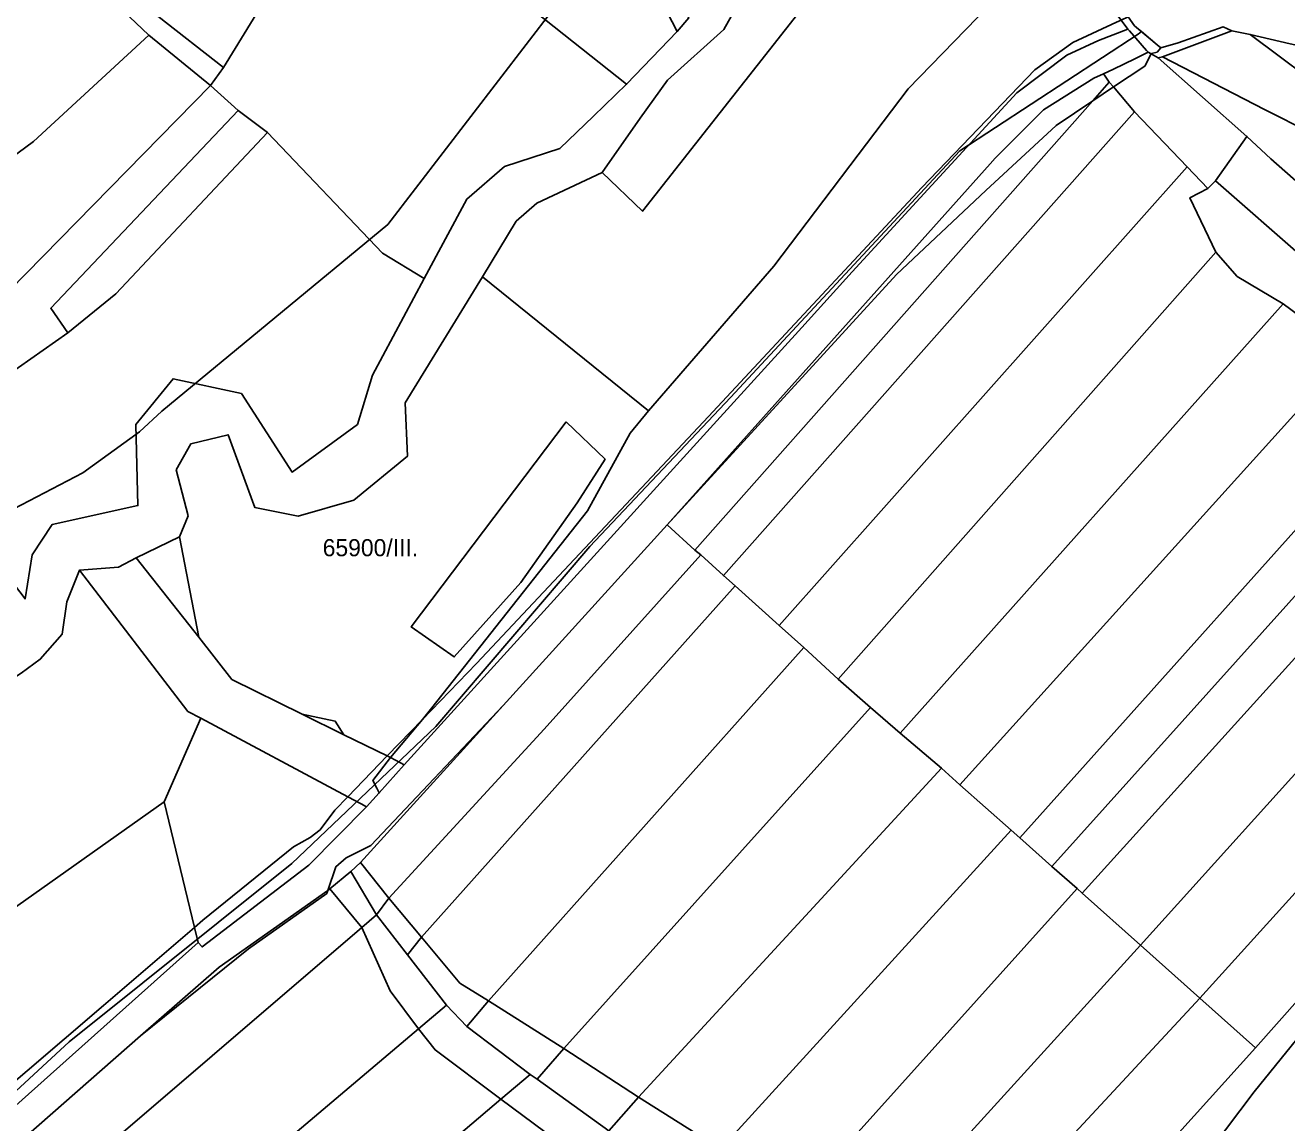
# Model space of a CAD drawing. Extents: x -521261 to -517465, y -1182764 to -1179456.
# Drawn here: x -519282.9 to -518914.6, y -1180365.6 to -1180045.4 of the extents above; entities that cross this region are included whole.
import ezdxf

# ---------------------------------------------------------------- set-up
doc = ezdxf.new("R2010")
doc.units = 0
for name, color, linetype in [('95560013', 7, 'Continuous'), ('95610013', 7, 'Continuous'), ('95630013', 7, 'Continuous'), ('95640013', 7, 'Continuous'), ('95660013', 7, 'Continuous')]:
    doc.layers.add(name, color=color, linetype=linetype)

msp = doc.modelspace()

# ---------------------------------------------------------------- linework, layer by layer
at = {"layer": '95560013'}
for points in [[(-519152.52, -1179936.19), (-519135.87, -1179962.09), (-519124.13, -1179989.34), (-519108.99, -1180015.26), (-519092.52, -1180047.19), (-519107.29, -1180062.58), (-519188.51, -1179998.17), (-519167.62, -1179960.77), (-519157.29, -1179942.3)], [(-519005.31, -1180000.63), (-518981.89, -1180013.42), (-518979.09, -1180016.92), (-518981.19, -1180020.04), (-518991.56, -1180029.33), (-519025.09, -1180063.9), (-519064.32, -1180115.7), (-519100.89, -1180157.88), (-519149.41, -1180118.82), (-519139.57, -1180102.58), (-519133.53, -1180097.26), (-519114.42, -1180088.31), (-519102.69, -1180099.64), (-519050.15, -1180032.84), (-519066.13, -1180023.9), (-519056.3, -1180015.44), (-519051.9, -1180002.3), (-519011.96, -1179982.64)], [(-518991.56, -1180029.33), (-518981.19, -1180020.04), (-518962.96, -1180043.91), (-518964.28, -1180044.51), (-518977.04, -1180050.38), (-518988.12, -1180058.41), (-519021.15, -1180092.68), (-519083.4, -1180159.52), (-519151.14, -1180231.61), (-519166.92, -1180247.95), (-519164.12, -1180244.58), (-519118.69, -1180187.09), (-519106.3, -1180164.45), (-519100.89, -1180157.88), (-519064.32, -1180115.7), (-519025.09, -1180063.9)], [(-519066.13, -1180023.9), (-519050.15, -1180032.84), (-519102.69, -1180099.64), (-519114.42, -1180088.31), (-519103.39, -1180072.53), (-519095.37, -1180061.41), (-519078.94, -1180046.61)], [(-518930.62, -1180047.06), (-518950.88, -1180054.57), (-518952.1, -1180054.93), (-518954.15, -1180053.76), (-518954.09, -1180053.64), (-518952.45, -1180053.19), (-518951.37, -1180051.98), (-518946.3, -1180050.48), (-518933.18, -1180045.84)], [(-518952.1, -1180054.93), (-518926.21, -1180077.8), (-518935.36, -1180090.75), (-518937.67, -1180092.99), (-518943.68, -1180086.68), (-518959.03, -1180070.69), (-518965.2, -1180063.4), (-518956.07, -1180057.3), (-518954.15, -1180053.76)], [(-518971.19, -1180067.41), (-518965.2, -1180063.4), (-518959.03, -1180070.69), (-519079.03, -1180205.95), (-519085.68, -1180199.95), (-519087.35, -1180198.58)], [(-518981.94, -1180074.6), (-518971.19, -1180067.41), (-519087.35, -1180198.58), (-519095.46, -1180191.17), (-519028.54, -1180118.15), (-519002.39, -1180093.57)], [(-518943.68, -1180086.68), (-519062.72, -1180220.58), (-519075.61, -1180208.96), (-519079.03, -1180205.95), (-518959.03, -1180070.69)], [(-519178.54, -1180111.93), (-519166.43, -1180119.32), (-519181.51, -1180147.48), (-519185.89, -1180161.84), (-519204.93, -1180175.78), (-519219.72, -1180152.85), (-519239.69, -1180148.52), (-519250.61, -1180161.86), (-519249.97, -1180185.55), (-519274.99, -1180191.09), (-519280.86, -1180199.88), (-519282.89, -1180212.77), (-519315.87, -1180169.61), (-519299.27, -1180155.36), (-519270.46, -1180135.11), (-519256.37, -1180123.73), (-519212.15, -1180076.64)], [(-518919.21, -1180084.38), (-518845.86, -1180148.96), (-518852.28, -1180156.99), (-518883.79, -1180135.9), (-518935.36, -1180090.75), (-518926.21, -1180077.8)], [(-518937.67, -1180092.99), (-518942.93, -1180095.78), (-518935.28, -1180111.55), (-519045.52, -1180236.19), (-519055.57, -1180226.99), (-519062.72, -1180220.58), (-518943.68, -1180086.68)], [(-518935.28, -1180111.55), (-518929.07, -1180118.68), (-518915.64, -1180126.65), (-519027.48, -1180251.97), (-519036.15, -1180244.45), (-519045.52, -1180236.19)], [(-519171.97, -1180155.54), (-519149.41, -1180118.82), (-519100.89, -1180157.88), (-519106.3, -1180164.45), (-519118.69, -1180187.09), (-519164.12, -1180244.58), (-519166.92, -1180247.95), (-519177.22, -1180258.6), (-519189.85, -1180252.44), (-519192.37, -1180248.47), (-519202.05, -1180246.4), (-519222.5, -1180236.25), (-519232.2, -1180223.95), (-519237.84, -1180194.65), (-519235.32, -1180188.57), (-519238.76, -1180175.07), (-519234.47, -1180167.48), (-519223.62, -1180164.85), (-519215.87, -1180186.06), (-519203.21, -1180188.59), (-519186.97, -1180183.94), (-519171.27, -1180171.17)], [(-518896.17, -1180141.1), (-519010.01, -1180267.06), (-519015.36, -1180262.2), (-519027.48, -1180251.97), (-518915.64, -1180126.65)], [(-518878.35, -1180155.06), (-518992.47, -1180282.53), (-518995.08, -1180280.28), (-519010.01, -1180267.06), (-518896.17, -1180141.1)], [(-518868.14, -1180162.99), (-518983.19, -1180290.9), (-518992.47, -1180282.53), (-518878.35, -1180155.06)], [(-519124.9, -1180161.11), (-519170.19, -1180220.96), (-519157.63, -1180229.7), (-519138.14, -1180208), (-519121.74, -1180184.72), (-519113.6, -1180172.01)], [(-519124.9, -1180161.11), (-519113.6, -1180172.01), (-519121.74, -1180184.72), (-519138.14, -1180208), (-519157.63, -1180229.7), (-519170.19, -1180220.96)], [(-518858.5, -1180170.71), (-518974.28, -1180298.61), (-518975.76, -1180297.28), (-518983.19, -1180290.9), (-518868.14, -1180162.99)], [(-518840.33, -1180184.24), (-518957.32, -1180313.77), (-518974.28, -1180298.61), (-518858.5, -1180170.71)], [(-518835.28, -1180187.7), (-518822.15, -1180199.1), (-518939.93, -1180329.25), (-518957.32, -1180313.77), (-518840.33, -1180184.24)], [(-519095.46, -1180191.17), (-519087.35, -1180198.58), (-519085.68, -1180199.95), (-519131.4, -1180250.79), (-519176.72, -1180300.12), (-519185.02, -1180289.7), (-519143.34, -1180243.85)], [(-519250.47, -1180200.79), (-519237.84, -1180194.65), (-519232.2, -1180223.95)], [(-518810.04, -1180209.46), (-518810.54, -1180215.99), (-518876.88, -1180291.05), (-518923.7, -1180343.73), (-518939.93, -1180329.25), (-518822.15, -1180199.1)], [(-519079.03, -1180205.95), (-519075.61, -1180208.96), (-519167.13, -1180311.47), (-519176.72, -1180300.12), (-519131.4, -1180250.79), (-519085.68, -1180199.95)], [(-519270.72, -1180213.62), (-519267, -1180204.34), (-519235.38, -1180245.61), (-519231.62, -1180247.61), (-519242.25, -1180271.95), (-519292.08, -1180307.22), (-519322.29, -1180336.38), (-519374.35, -1180291.1), (-519337.72, -1180282.23), (-519327.14, -1180275.48), (-519322.14, -1180255.98), (-519303.81, -1180244.74), (-519294.17, -1180241.09), (-519284, -1180234.4), (-519278.49, -1180230.4), (-519272.1, -1180223.08)], [(-519062.72, -1180220.58), (-519055.57, -1180226.99), (-519147.65, -1180330.09), (-519156.01, -1180324.9), (-519167.13, -1180311.47), (-519075.61, -1180208.96)], [(-519055.57, -1180226.99), (-519045.52, -1180236.19), (-519036.15, -1180244.45), (-519125.66, -1180344.01), (-519147.65, -1180330.09)], [(-519192.37, -1180248.47), (-519189.85, -1180252.44), (-519202.05, -1180246.4)], [(-519036.15, -1180244.45), (-519027.48, -1180251.97), (-519015.36, -1180262.2), (-519103.8, -1180358.17), (-519125.66, -1180344.01)], [(-519231.62, -1180247.61), (-519188.71, -1180270.5), (-519192.5, -1180274.43), (-519196.77, -1180280.19), (-519199.69, -1180282.36), (-519204.49, -1180285.08), (-519231.03, -1180306.54), (-519233.45, -1180308.61), (-519242.25, -1180271.95)], [(-519010.01, -1180267.06), (-518995.08, -1180280.28), (-519082.74, -1180376.5), (-519085.15, -1180369.94), (-519103.8, -1180358.17), (-519015.36, -1180262.2)], [(-519242.25, -1180271.95), (-519233.45, -1180308.61), (-519259.97, -1180331.39), (-519293.87, -1180360.31), (-519294.53, -1180360.9), (-519322.29, -1180336.38), (-519292.08, -1180307.22)], [(-518995.08, -1180280.28), (-518992.47, -1180282.53), (-518983.19, -1180290.9), (-518975.76, -1180297.28), (-519071.7, -1180403.95), (-519082.74, -1180376.5)], [(-518872.62, -1180293.06), (-518924.13, -1180356.64), (-518966.24, -1180412.4), (-518988.53, -1180447.41), (-519008.28, -1180481.84), (-519035.64, -1180467.78), (-518923.7, -1180343.73), (-518876.88, -1180291.05)], [(-519194.54, -1180297.83), (-519193.89, -1180297.38), (-519184.62, -1180308.69), (-519272, -1180383.57), (-519277.33, -1180375.77), (-519282.81, -1180369.73), (-519249.16, -1180340.26), (-519217.64, -1180314.85), (-519194.84, -1180298.72)], [(-518975.76, -1180297.28), (-518974.28, -1180298.61), (-518957.32, -1180313.77), (-519062.09, -1180429.12), (-519071.7, -1180403.95)], [(-519184.62, -1180308.69), (-519176.29, -1180327.1), (-519168.04, -1180338.25), (-519255.35, -1180412.02), (-519265.72, -1180393.34), (-519272, -1180383.57)], [(-518939.93, -1180329.25), (-519053.22, -1180451.28), (-519062.09, -1180429.12), (-518957.32, -1180313.77)], [(-518923.7, -1180343.73), (-519035.64, -1180467.78), (-519050.07, -1180460), (-519053.22, -1180451.28), (-518939.93, -1180329.25)], [(-519168.04, -1180338.25), (-519163.2, -1180344.4), (-519144.03, -1180358.73), (-519240.36, -1180440.61), (-519255.35, -1180412.02)], [(-519144.03, -1180358.73), (-519121.36, -1180375.58), (-519223.33, -1180463.53), (-519233.13, -1180450.99), (-519240.36, -1180440.61)]]:
    msp.add_lwpolyline(points, close=True, dxfattribs=at)
msp.add_lwpolyline([(-518912.15, -1180557.37), (-518933.81, -1180591.04), (-518938.01, -1180602.29), (-518951.28, -1180590.32), (-518960.78, -1180581.34), (-518962.6, -1180579.56), (-518964.48, -1180579.13), (-518975.87, -1180577.02), (-518981.52, -1180575.61), (-519013.54, -1180518.68), (-519017.95, -1180511.02), (-519021.16, -1180506.1), (-519008.28, -1180481.84), (-518988.53, -1180447.41), (-518966.24, -1180412.4), (-518924.13, -1180356.64), (-518872.62, -1180293.06)], dxfattribs=at)
at = {"layer": '95610013'}
for points in [[(-519148.09, -1179930.61), (-519133.74, -1179959.32), (-519089.17, -1180043.17), (-519092.52, -1180047.19), (-519108.99, -1180015.26), (-519124.13, -1179989.34), (-519135.87, -1179962.09), (-519152.52, -1179936.19), (-519150.51, -1179933.54)], [(-519224.99, -1180057.71), (-519188.51, -1179998.17), (-519107.29, -1180062.58), (-519116.98, -1180071.93), (-519126.81, -1180081.34), (-519142.9, -1180086.6), (-519153.96, -1180096.09), (-519166.43, -1180119.32), (-519178.54, -1180111.93), (-519212.15, -1180076.64), (-519220.73, -1180070.29), (-519228.73, -1180062.96)], [(-519281.14, -1180021.48), (-519276.5, -1180019.95), (-519246.76, -1180048.25), (-519280.42, -1180079.34), (-519302.56, -1180095.53), (-519322.25, -1180063.62)], [(-519228.73, -1180062.96), (-519287.48, -1180122.75), (-519293.8, -1180120.73), (-519320.09, -1180144.01), (-519347.22, -1180172.54), (-519361.3, -1180177.13), (-519382.09, -1180196.89), (-519381.36, -1180152.77), (-519348.46, -1180129.53), (-519302.56, -1180095.53), (-519280.42, -1180079.34), (-519246.76, -1180048.25)], [(-518930.62, -1180047.06), (-518925.25, -1180048.07), (-518850.28, -1180104.06), (-518847.22, -1180107.51), (-518833.18, -1180123.22), (-518814.68, -1180148.98), (-518823.68, -1180155.62), (-518894, -1180083.54), (-518921.09, -1180070), (-518950.88, -1180054.57)], [(-518913.62, -1180050.8), (-518880.77, -1180057.74), (-518867.6, -1180073.76), (-518855.92, -1180097.31), (-518850.28, -1180104.06), (-518925.25, -1180048.07)], [(-519228.73, -1180062.96), (-519220.73, -1180070.29), (-519275.39, -1180127.98), (-519270.46, -1180135.11), (-519299.27, -1180155.36), (-519315.87, -1180169.61), (-519334.56, -1180185.51), (-519347.22, -1180172.54), (-519320.09, -1180144.01), (-519293.8, -1180120.73), (-519287.48, -1180122.75)], [(-519212.15, -1180076.64), (-519256.37, -1180123.73), (-519270.46, -1180135.11), (-519275.39, -1180127.98), (-519220.73, -1180070.29)], [(-518935.36, -1180090.75), (-518883.79, -1180135.9), (-518852.28, -1180156.99), (-518845.86, -1180148.96), (-518820.97, -1180171.01), (-518835.28, -1180187.7), (-518840.33, -1180184.24), (-518858.5, -1180170.71), (-518868.14, -1180162.99), (-518878.35, -1180155.06), (-518896.17, -1180141.1), (-518915.64, -1180126.65), (-518929.07, -1180118.68), (-518935.28, -1180111.55), (-518942.93, -1180095.78), (-518937.67, -1180092.99)]]:
    msp.add_lwpolyline(points, close=True, dxfattribs=at)
at = {"layer": '95630013'}
for points in [[(-519066.13, -1180023.9), (-519078.94, -1180046.61), (-519095.37, -1180061.41), (-519103.39, -1180072.53), (-519114.42, -1180088.31), (-519133.53, -1180097.26), (-519139.57, -1180102.58), (-519149.41, -1180118.82), (-519171.97, -1180155.54), (-519171.27, -1180171.17), (-519186.97, -1180183.94), (-519203.21, -1180188.59), (-519215.87, -1180186.06), (-519223.62, -1180164.85), (-519234.47, -1180167.48), (-519238.76, -1180175.07), (-519235.32, -1180188.57), (-519237.84, -1180194.65), (-519250.47, -1180200.79), (-519255.66, -1180203.54), (-519267, -1180204.34), (-519270.72, -1180213.62), (-519272.1, -1180223.08), (-519278.49, -1180230.4), (-519284, -1180234.4)], [(-519282.89, -1180212.77), (-519280.86, -1180199.88), (-519274.99, -1180191.09), (-519249.97, -1180185.55), (-519250.61, -1180161.86), (-519239.69, -1180148.52), (-519219.72, -1180152.85), (-519204.93, -1180175.78), (-519185.89, -1180161.84), (-519181.51, -1180147.48), (-519166.43, -1180119.32), (-519153.96, -1180096.09), (-519142.9, -1180086.6), (-519126.81, -1180081.34), (-519116.98, -1180071.93), (-519107.29, -1180062.58), (-519092.52, -1180047.19), (-519089.17, -1180043.17)]]:
    msp.add_lwpolyline(points, dxfattribs=at)
at = {"layer": '95640013'}
for points in [[(-519238.71, -1179905.52), (-519167.62, -1179960.77), (-519188.51, -1179998.17), (-519224.99, -1180057.71), (-519263.35, -1180027.7), (-519253.07, -1180008.97), (-519277.89, -1179987.4), (-519269.76, -1179928.77)], [(-519269.76, -1179928.77), (-519277.89, -1179987.4), (-519253.07, -1180008.97), (-519263.35, -1180027.7), (-519224.99, -1180057.71), (-519228.73, -1180062.96), (-519246.76, -1180048.25), (-519276.5, -1180019.95), (-519270.16, -1180015.03), (-519283.83, -1179998.93), (-519283.91, -1179987.19), (-519300.93, -1179970.23), (-519313.5, -1179963.8), (-519307.71, -1179957.39), (-519283.01, -1179978.66), (-519275.76, -1179931.8)], [(-518964.28, -1180044.51), (-518962.96, -1180043.91), (-518960.94, -1180046.56), (-518969.59, -1180049.8), (-518978.82, -1180054.08), (-518993.41, -1180065.09), (-519021.6, -1180095.76), (-519041.41, -1180117.31), (-519056.19, -1180133.53), (-519081.98, -1180161.91), (-519172.27, -1180261.16), (-519173.26, -1180260.64), (-519176.21, -1180259.09), (-519166.92, -1180247.95), (-519151.14, -1180231.61), (-519083.4, -1180159.52), (-519021.15, -1180092.68), (-518988.12, -1180058.41), (-518977.04, -1180050.38)], [(-518962.96, -1180043.91), (-518960.91, -1180042.97), (-518959.01, -1180045.58), (-518958.48, -1180046.02), (-518952.45, -1180051.06), (-518951.37, -1180051.98), (-518952.45, -1180053.19), (-518954.09, -1180053.64), (-518954.15, -1180053.76), (-518955.08, -1180053.23), (-518955.5, -1180052.76), (-518960.54, -1180047), (-518960.94, -1180046.56)], [(-518954.15, -1180053.76), (-518956.07, -1180057.3), (-518965.2, -1180063.4), (-518966.39, -1180061.99), (-518967.84, -1180059.94), (-518968.09, -1180059.58), (-518965.21, -1180058.19), (-518958.95, -1180055.16), (-518955.08, -1180053.23)], [(-518952.1, -1180054.93), (-518950.88, -1180054.57), (-518921.09, -1180070), (-518894, -1180083.54), (-518823.68, -1180155.62), (-518814.68, -1180148.98), (-518784, -1180192.42), (-518790.12, -1180198.06), (-518801.96, -1180187.97), (-518820.97, -1180171.01), (-518845.86, -1180148.96), (-518919.21, -1180084.38), (-518926.21, -1180077.8)], [(-518967.84, -1180059.94), (-518966.39, -1180061.99), (-518971.19, -1180067.41), (-518981.94, -1180074.6), (-519002.39, -1180093.57), (-519028.54, -1180118.15), (-519095.46, -1180191.17), (-519001.18, -1180085.81), (-518999.73, -1180084.19), (-518985.57, -1180070.02), (-518970.94, -1180060.85), (-518968.09, -1180059.58)], [(-518965.2, -1180063.4), (-518971.19, -1180067.41), (-518966.39, -1180061.99)], [(-519255.66, -1180203.54), (-519250.47, -1180200.79), (-519232.2, -1180223.95), (-519222.5, -1180236.25), (-519202.05, -1180246.4), (-519189.85, -1180252.44), (-519177.22, -1180258.6), (-519188.71, -1180270.5), (-519231.62, -1180247.61), (-519235.38, -1180245.61), (-519267, -1180204.34)], [(-519143.34, -1180243.85), (-519185.02, -1180289.7), (-519187.77, -1180292.28), (-519193.89, -1180297.38), (-519194.54, -1180297.83), (-519192.22, -1180290.94), (-519189.12, -1180288.35), (-519181.98, -1180284.71)], [(-519177.22, -1180258.6), (-519166.92, -1180247.95), (-519176.21, -1180259.09)], [(-519177.22, -1180258.6), (-519176.21, -1180259.09), (-519181.41, -1180265.73), (-519180.24, -1180268), (-519179.53, -1180269.37), (-519183.22, -1180273.43), (-519184.76, -1180272.6), (-519188.71, -1180270.5)], [(-519176.21, -1180259.09), (-519173.26, -1180260.64), (-519172.27, -1180261.16), (-519179.53, -1180269.37), (-519180.24, -1180268), (-519181.41, -1180265.73)], [(-519188.71, -1180270.5), (-519184.76, -1180272.6), (-519183.22, -1180273.43), (-519200.05, -1180290.51), (-519231.22, -1180314.34), (-519232.4, -1180313), (-519233.45, -1180308.61), (-519231.03, -1180306.54), (-519204.49, -1180285.08), (-519199.69, -1180282.36), (-519196.77, -1180280.19), (-519192.5, -1180274.43)], [(-519185.02, -1180289.7), (-519176.72, -1180300.12), (-519180.35, -1180304.92), (-519187.77, -1180292.28)], [(-519187.77, -1180292.28), (-519180.35, -1180304.92), (-519184.62, -1180308.69), (-519193.89, -1180297.38)], [(-519194.54, -1180297.83), (-519194.84, -1180298.72), (-519217.64, -1180314.85), (-519249.16, -1180340.26), (-519226.25, -1180320.2)], [(-519180.35, -1180304.92), (-519176.72, -1180300.12), (-519167.13, -1180311.47), (-519171.29, -1180316.65)], [(-519180.35, -1180304.92), (-519171.29, -1180316.65), (-519159.9, -1180331.28), (-519168.04, -1180338.25), (-519176.29, -1180327.1), (-519184.62, -1180308.69)], [(-519233.45, -1180308.61), (-519232.4, -1180313), (-519290.28, -1180364.64), (-519292.52, -1180362.68), (-519294.53, -1180360.9), (-519293.87, -1180360.31), (-519259.97, -1180331.39)], [(-519171.29, -1180316.65), (-519167.13, -1180311.47), (-519156.01, -1180324.9), (-519147.65, -1180330.09), (-519153.96, -1180337.55), (-519159.9, -1180331.28)], [(-519153.96, -1180337.55), (-519135.45, -1180351.52), (-519144.03, -1180358.73), (-519163.2, -1180344.4), (-519168.04, -1180338.25), (-519159.9, -1180331.28)], [(-519153.96, -1180337.55), (-519147.65, -1180330.09), (-519125.66, -1180344.01), (-519133.4, -1180352.94), (-519135.45, -1180351.52)], [(-519133.4, -1180352.94), (-519125.66, -1180344.01), (-519103.8, -1180358.17), (-519112.46, -1180368.03)], [(-519133.4, -1180352.94), (-519112.46, -1180368.03), (-519121.36, -1180375.58), (-519144.03, -1180358.73), (-519135.45, -1180351.52)], [(-519112.46, -1180368.03), (-519103.8, -1180358.17), (-519085.15, -1180369.94), (-519082.74, -1180376.5), (-519094.78, -1180390.49), (-519096.69, -1180388.33)]]:
    msp.add_lwpolyline(points, close=True, dxfattribs=at)
msp.add_lwpolyline([(-519290.28, -1180364.64), (-519232.4, -1180313), (-519231.22, -1180314.34), (-519200.05, -1180290.51), (-519183.22, -1180273.43), (-519179.53, -1180269.37), (-519172.27, -1180261.16), (-519081.98, -1180161.91), (-519056.19, -1180133.53), (-519041.41, -1180117.31), (-519021.6, -1180095.76), (-518993.41, -1180065.09), (-518978.82, -1180054.08), (-518969.59, -1180049.8), (-518960.94, -1180046.56), (-518960.54, -1180047), (-518955.5, -1180052.76), (-518955.08, -1180053.23), (-518958.95, -1180055.16), (-518965.21, -1180058.19), (-518968.09, -1180059.58), (-518970.94, -1180060.85), (-518985.57, -1180070.02), (-518999.73, -1180084.19), (-519001.18, -1180085.81), (-519095.46, -1180191.17), (-519143.34, -1180243.85), (-519181.98, -1180284.71), (-519189.12, -1180288.35), (-519192.22, -1180290.94), (-519194.54, -1180297.83), (-519226.25, -1180320.2), (-519249.16, -1180340.26), (-519282.81, -1180369.73)], dxfattribs=at)
at = {"layer": '95660013'}
for points in [[(-519128.5, -1180040.5), (-519177, -1180103.5), (-519243, -1180158), (-519249.5, -1180164), (-519266, -1180176), (-519293, -1180190), (-519321.5, -1180205), (-519337, -1180214), (-519361.5, -1180222.5), (-519435, -1180243), (-519517, -1180253.5), (-519555.5, -1180255.5), (-519586, -1180250), (-519615, -1180239.5), (-519633.5, -1180230), (-519675.5, -1180194.5), (-519712.5, -1180155), (-519732.5, -1180127.5), (-519743.5, -1180109), (-519761, -1180089), (-519772, -1180081)], [(-519293, -1180190), (-519266, -1180176), (-519249.5, -1180164), (-519243, -1180158), (-519177, -1180103.5), (-519128.5, -1180040.5)], [(-518960.91, -1180042.97), (-518959.01, -1180045.58), (-518958.48, -1180046.02), (-518957.04, -1180047.22), (-518958, -1180048), (-519010, -1180082), (-519077, -1180154), (-519118, -1180197.5), (-519163, -1180250), (-519205, -1180290), (-519270, -1180342), (-519322, -1180390)], [(-519383.5, -1180567.5), (-519420, -1180508), (-519396.5, -1180466.5), (-519369, -1180434), (-519322, -1180390), (-519270, -1180342), (-519205, -1180290), (-519163, -1180250), (-519118, -1180197.5), (-519077, -1180154), (-519010, -1180082), (-518958, -1180048), (-518957.04, -1180047.22), (-518952.45, -1180051.06), (-518951.37, -1180051.98), (-518946.3, -1180050.48), (-518933.18, -1180045.84), (-518930.62, -1180047.06), (-518925.25, -1180048.07), (-518913.62, -1180050.8)], [(-519121.36, -1180375.58), (-519144.03, -1180358.73), (-519163.2, -1180344.4), (-519168.04, -1180338.25), (-519176.29, -1180327.1), (-519184.62, -1180308.69), (-519193.89, -1180297.38), (-519187.77, -1180292.28), (-519185.02, -1180289.7), (-519176.72, -1180300.12), (-519167.13, -1180311.47), (-519156.01, -1180324.9), (-519147.65, -1180330.09), (-519125.66, -1180344.01), (-519103.8, -1180358.17), (-519085.15, -1180369.94)], [(-519085.15, -1180369.94), (-519103.8, -1180358.17), (-519125.66, -1180344.01), (-519147.65, -1180330.09), (-519156.01, -1180324.9), (-519167.13, -1180311.47), (-519176.72, -1180300.12), (-519185.02, -1180289.7), (-519187.77, -1180292.28), (-519193.89, -1180297.38), (-519184.62, -1180308.69), (-519176.29, -1180327.1), (-519168.04, -1180338.25), (-519163.2, -1180344.4), (-519144.03, -1180358.73), (-519121.36, -1180375.58)]]:
    msp.add_lwpolyline(points, dxfattribs=at)

# ---------------------------------------------------------------- texts
msp.add_text('65900/III.', height=5, rotation=360, dxfattribs=at).set_placement((-519196.02, -1180200.33))

doc.saveas('drawing.dxf')
